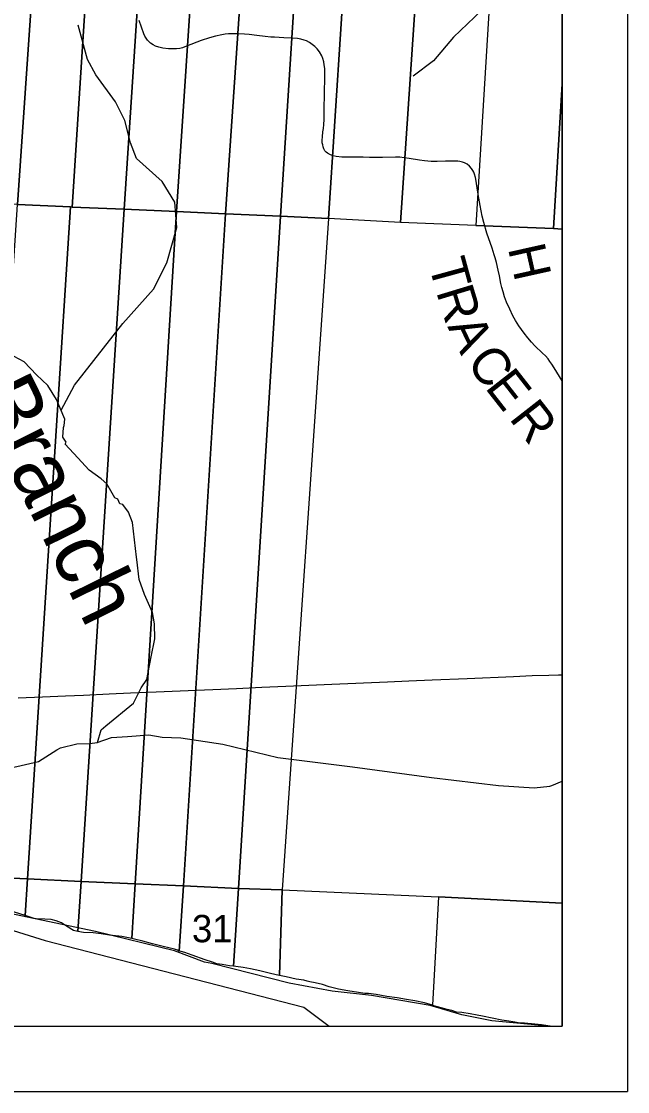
# Model space of a CAD drawing. Extents: x -2.1 to 31.9, y 6.3 to 28.3.
# Drawn here: x 6.006 to 6.934, y 20.344 to 21.982 of the extents above; entities that cross this region are included whole.
import ezdxf

# ---------------------------------------------------------------- set-up
doc = ezdxf.new("R2010")
doc.units = 0
for name, color, linetype in [('Default', 7, 'Continuous'), ('GM_X_County_Road', 7, 'Continuous'), ('GM_X_County_Road_Text', 7, 'Continuous'), ('GM_X_Major_River', 7, 'Continuous'), ('GM_X_Minor_River', 7, 'Continuous'), ('GM_X_Minor_River_Text', 7, 'Continuous'), ('GM_X_Section', 7, 'Continuous'), ('GM_X_Section_Text', 7, 'Continuous'), ('GM_X_State_Route', 7, 'Continuous'), ('SH_Cut_Line', 7, 'Continuous'), ('SH_Data', 7, 'Continuous')]:
    doc.layers.add(name, color=color, linetype=linetype)

msp = doc.modelspace()

# ---------------------------------------------------------------- linework, layer by layer
at = {"layer": 'Default'}
msp.add_lwpolyline([(5.1462, 20.8673), (5.351, 20.8306), (5.3336, 20.8064), (5.2334, 20.7804), (5.2354, 20.7659), (5.3321, 20.7189), (5.4454, 20.7228), (5.4488, 20.7357), (5.4242, 20.7435), (5.4528, 20.7586), (5.5937, 20.7278), (5.7973, 20.6518), (6.0426, 20.5752), (6.4385, 20.4731), (6.4775, 20.444), (6.8344, 20.444), (6.8344, 25.7721)], dxfattribs=at)
for points in [[(6.8344, 21.8866), (6.8344, 22.7109), (6.7658, 22.714), (6.7023, 21.67), (6.8212, 21.6651)], [(6.8344, 21.6645), (6.8344, 21.8866), (6.8212, 21.6651)], [(6.8344, 20.6325), (6.8344, 21.6645), (6.8212, 21.6651), (6.7023, 21.67), (6.5865, 21.6746), (6.4767, 21.6808), (6.4057, 20.6526), (6.645, 20.6422)], [(6.82, 20.444), (6.8344, 20.444), (6.8344, 20.6325), (6.645, 20.6422), (6.6359, 20.4764), (6.643, 20.4742), (6.654, 20.4712), (6.665, 20.4686), (6.6722, 20.4663), (6.6805, 20.4656), (6.6934, 20.4634), (6.7041, 20.4615), (6.7124, 20.4597), (6.7272, 20.4567), (6.742, 20.4537), (6.7526, 20.4522), (6.7617, 20.4507), (6.767, 20.4496), (6.7768, 20.4493), (6.7875, 20.4482), (6.8026, 20.4467), (6.8189, 20.4441)]]:
    msp.add_lwpolyline(points, close=True, dxfattribs=at)
at = {"layer": 'GM_X_County_Road'}
msp.add_lwpolyline([(6.8344, 21.4322), (6.8219, 21.4519), (6.8182, 21.4575), (6.8155, 21.4615), (6.8126, 21.4657), (6.8086, 21.4704), (6.8042, 21.4746), (6.7925, 21.4857), (6.7873, 21.4911), (6.7815, 21.4977), (6.7759, 21.5049), (6.768, 21.5163), (6.7627, 21.5246), (6.7589, 21.5315), (6.7539, 21.5418), (6.7492, 21.5525), (6.7461, 21.5606), (6.7437, 21.5684), (6.7419, 21.5748), (6.7406, 21.5809), (6.7382, 21.5927), (6.7363, 21.6016), (6.7338, 21.613), (6.7317, 21.6205), (6.7303, 21.6248), (6.7269, 21.6353), (6.7191, 21.6583), (6.7144, 21.6743), (6.7119, 21.6843), (6.7089, 21.7007), (6.7067, 21.7119), (6.7047, 21.7241), (6.7025, 21.738), (6.7015, 21.7433), (6.7001, 21.7483), (6.6989, 21.7514), (6.6977, 21.754), (6.6957, 21.7571), (6.6925, 21.7609), (6.6888, 21.7637), (6.6846, 21.7657), (6.6816, 21.7669), (6.6778, 21.7679), (6.6747, 21.7683), (6.6712, 21.7686), (6.6638, 21.7686), (6.6557, 21.7682), (6.6427, 21.7678), (6.6339, 21.768), (6.6237, 21.7687), (6.6156, 21.7697), (6.5999, 21.7727), (6.5924, 21.7736), (6.5857, 21.7743), (6.5789, 21.7745), (6.5591, 21.7742), (6.5394, 21.7742), (6.5297, 21.7744), (6.5092, 21.7744), (6.4967, 21.7747), (6.488, 21.7756), (6.4836, 21.7766), (6.4795, 21.778), (6.475, 21.7804), (6.473, 21.782), (6.471, 21.7844), (6.4694, 21.7874), (6.4683, 21.7903), (6.4676, 21.7934), (6.467, 21.7966), (6.467, 21.8006), (6.4674, 21.8054), (6.468, 21.8131), (6.4687, 21.8185), (6.4692, 21.8244), (6.4697, 21.8324), (6.4699, 21.8454), (6.4703, 21.8738), (6.471, 21.8954), (6.4709, 21.9046), (6.4707, 21.9101), (6.4701, 21.9158), (6.4692, 21.9206), (6.4679, 21.9254), (6.4663, 21.9295), (6.4626, 21.9358), (6.4592, 21.9402), (6.4555, 21.9441), (6.4515, 21.9471), (6.4474, 21.9498), (6.4426, 21.9524), (6.4392, 21.9538), (6.434, 21.9552), (6.4289, 21.956), (6.4203, 21.9569), (6.4079, 21.9574), (6.3936, 21.958), (6.3881, 21.9584), (6.3794, 21.9591), (6.3669, 21.9607), (6.3549, 21.9622), (6.3477, 21.9629), (6.3384, 21.9634), (6.33, 21.9635), (6.3234, 21.9631), (6.3184, 21.9626), (6.3132, 21.9617), (6.3036, 21.9596), (6.2942, 21.9571), (6.2817, 21.9529), (6.259, 21.9443), (6.2529, 21.9421), (6.2489, 21.9408), (6.2437, 21.9404), (6.2389, 21.9402), (6.2313, 21.9406), (6.223, 21.9415), (6.2167, 21.9428), (6.2115, 21.9446), (6.2082, 21.9463), (6.204, 21.9491), (6.1996, 21.9536), (6.1973, 21.9569), (6.1955, 21.9598), (6.194, 21.9631), (6.1903, 21.9734), (6.1868, 21.9839)], dxfattribs=at)
at = {"layer": 'GM_X_Major_River'}
msp.add_lwpolyline([(6.8077, 20.444), (6.7977, 20.4457), (6.7264, 20.4524), (6.6809, 20.4615), (6.6324, 20.4758), (6.5422, 20.4913), (6.4819, 20.4976), (6.4163, 20.5101), (6.298, 20.5403), (6.2866, 20.5421), (6.2408, 20.5595), (6.1198, 20.5893), (5.9765, 20.6191)], dxfattribs=at)
at = {"layer": 'GM_X_Minor_River'}
for points in [[(6.8344, 22.0788), (6.8176, 22.0793), (6.7959, 22.0736), (6.7763, 22.0632), (6.7589, 22.0493), (6.7396, 22.0359), (6.7109, 21.9992), (6.6681, 21.9584), (6.6371, 21.9222), (6.6061, 21.8985)], [(6.0672, 21.3872), (6.0875, 21.4257), (6.1618, 21.5201), (6.2084, 21.5726), (6.2289, 21.6125), (6.2442, 21.6667), (6.2412, 21.7055), (6.2221, 21.7373), (6.1827, 21.7727), (6.1732, 21.7962), (6.1648, 21.8306), (6.1506, 21.8592), (6.1205, 21.9004), (6.1076, 21.924), (6.0933, 21.9764)], [(5.9565, 20.8322), (6.0124, 20.8449), (6.0325, 20.8495), (6.0608, 20.8671), (6.0661, 20.8701), (6.0914, 20.8763), (6.1107, 20.8771), (6.1228, 20.8786), (6.1284, 20.898), (6.1356, 20.9037), (6.1779, 20.9384), (6.1896, 20.962), (6.1983, 20.9746), (6.2051, 21.0095), (6.2107, 21.0373), (6.2103, 21.0601), (6.2069, 21.0776), (6.1948, 21.1049), (6.1868, 21.1277), (6.183, 21.1588), (6.1826, 21.1623), (6.1765, 21.2154), (6.1701, 21.231), (6.1618, 21.2428), (6.1569, 21.2439), (6.1538, 21.2507), (6.1493, 21.253), (6.1372, 21.2746), (6.1285, 21.2818), (6.1103, 21.2955), (6.0925, 21.3144), (6.0736, 21.3349), (6.0747, 21.3384), (6.0698, 21.3459), (6.0706, 21.3604), (6.0717, 21.3638), (6.0728, 21.3733), (6.0603, 21.4037), (6.0467, 21.4249), (6.0297, 21.4412), (6.0104, 21.461), (5.9952, 21.4693)], [(6.1225, 20.8786), (6.1443, 20.8859), (6.1689, 20.8875), (6.2014, 20.8902), (6.2218, 20.8864), (6.2505, 20.8854), (6.3148, 20.8756), (6.3991, 20.8553), (6.5133, 20.8411), (6.6343, 20.8247), (6.7368, 20.8124), (6.7916, 20.8091), (6.8154, 20.8118), (6.8184, 20.8125), (6.8344, 20.8191)]]:
    msp.add_lwpolyline(points, dxfattribs=at)
at = {"layer": 'GM_X_Section'}
for points in [[(6.0723, 22.7483), (6.0006, 21.7019), (5.9213, 21.7055), (5.9912, 22.7527)], [(6.1513, 22.7445), (6.0839, 21.6982), (6.0813, 21.6984), (6.0006, 21.7019), (6.0723, 22.7483)], [(6.2319, 22.7402), (6.1637, 21.6947), (6.0839, 21.6982), (6.1513, 22.7445)], [(6.313, 22.7362), (6.2438, 21.6911), (6.1637, 21.6947), (6.2319, 22.7402)], [(6.3902, 22.7322), (6.3189, 21.6878), (6.2438, 21.6911), (6.313, 22.7362)], [(6.4695, 22.728), (6.4029, 21.6841), (6.3189, 21.6878), (6.3902, 22.7322)], [(6.5442, 22.7242), (6.4767, 21.6808), (6.4029, 21.6841), (6.4695, 22.728)], [(6.6574, 22.719), (6.5865, 21.6746), (6.4767, 21.6808), (6.5442, 22.7242)], [(6.7658, 22.714), (6.7023, 21.67), (6.5865, 21.6746), (6.6574, 22.719)], [(6.0813, 21.6984), (6.0156, 20.6695), (5.933, 20.6732), (6.0006, 21.7019)], [(6.0839, 21.6982), (6.1637, 21.6947), (6.0979, 20.6658), (6.0156, 20.6695), (6.0813, 21.6984)], [(6.2438, 21.6911), (6.1805, 20.6622), (6.0979, 20.6658), (6.1637, 21.6947)], [(6.3189, 21.6878), (6.2543, 20.6589), (6.1805, 20.6622), (6.2438, 21.6911)], [(6.4029, 21.6841), (6.3388, 20.6551), (6.2543, 20.6589), (6.3189, 21.6878)], [(6.4767, 21.6808), (6.4057, 20.6526), (6.3388, 20.6551), (6.4029, 21.6841)], [(6.0156, 20.6695), (6.012, 20.6134), (5.9957, 20.6186), (5.9862, 20.6204), (5.979, 20.6215), (5.973, 20.623), (5.9616, 20.626), (5.954, 20.6283), (5.9438, 20.6324), (5.9347, 20.6354), (5.9306, 20.6368), (5.933, 20.6732)], [(6.0979, 20.6658), (6.0929, 20.589), (6.086, 20.5908), (6.0837, 20.5923), (6.0723, 20.5995), (6.0678, 20.6021), (6.0594, 20.6055), (6.0518, 20.6074), (6.0423, 20.6081), (6.0287, 20.6084), (6.0257, 20.6092), (6.0211, 20.6107), (6.012, 20.6134), (6.0156, 20.6695)], [(6.1805, 20.6622), (6.1754, 20.5785), (6.1679, 20.5801), (6.1603, 20.5812), (6.1459, 20.5827), (6.141, 20.5835), (6.1284, 20.5853), (6.1163, 20.5868), (6.1012, 20.5875), (6.0929, 20.589), (6.0979, 20.6658)], [(6.2543, 20.6589), (6.248, 20.5588), (6.2452, 20.5603), (6.2407, 20.5618), (6.2236, 20.5663), (6.2073, 20.5704), (6.1921, 20.5742), (6.1796, 20.5775), (6.1754, 20.5785), (6.1805, 20.6622)], [(6.3388, 20.6551), (6.3313, 20.5359), (6.3249, 20.5364), (6.3135, 20.5386), (6.3055, 20.5397), (6.2987, 20.5419), (6.2877, 20.5457), (6.268, 20.5528), (6.2566, 20.557), (6.2509, 20.5585), (6.248, 20.5588), (6.2543, 20.6589)], [(6.4057, 20.6526), (6.4017, 20.5217), (6.3966, 20.5228), (6.3855, 20.5252), (6.3715, 20.5289), (6.3571, 20.5319), (6.3457, 20.5338), (6.3344, 20.5356), (6.3313, 20.5359), (6.3388, 20.6551)], [(6.4057, 20.6526), (6.645, 20.6422), (6.6359, 20.4764), (6.6233, 20.4798), (6.6085, 20.4828), (6.596, 20.485), (6.5816, 20.4876), (6.566, 20.4898), (6.5494, 20.4924), (6.5376, 20.4939), (6.5323, 20.4939), (6.5224, 20.4957), (6.5061, 20.4983), (6.4917, 20.5009), (6.4773, 20.5043), (6.4671, 20.5077), (6.4561, 20.5107), (6.4481, 20.5122), (6.4436, 20.5129), (6.439, 20.5144), (6.4269, 20.5163), (6.4117, 20.5196), (6.4017, 20.5217)]]:
    msp.add_lwpolyline(points, close=True, dxfattribs=at)
at = {"layer": 'GM_X_State_Route'}
msp.add_lwpolyline([(6.0012, 20.9468), (6.0385, 20.9484), (6.0739, 20.95), (6.1016, 20.9511), (6.1409, 20.9528), (6.1732, 20.9542), (6.2126, 20.956), (6.2618, 20.958), (6.2995, 20.9597), (6.3356, 20.9613), (6.3747, 20.9629), (6.4113, 20.9645), (6.4814, 20.9677), (6.5671, 20.9713), (6.5997, 20.9727), (6.6354, 20.9741), (6.6888, 20.9765), (6.7595, 20.9795), (6.7881, 20.9808), (6.8137, 20.9816), (6.8285, 20.9819), (6.8344, 20.9819)], dxfattribs=at)
at = {"layer": 'SH_Cut_Line'}
msp.add_lwpolyline([(5.1462, 20.8673), (5.351, 20.8306), (5.3336, 20.8064), (5.2334, 20.7804), (5.2354, 20.7659), (5.3321, 20.7189), (5.4454, 20.7228), (5.4488, 20.7357), (5.4242, 20.7435), (5.4528, 20.7586), (5.5937, 20.7278), (5.7973, 20.6518), (6.0426, 20.5752), (6.4385, 20.4731), (6.4775, 20.444), (6.8344, 20.444), (6.8344, 27.244)], dxfattribs=at)
at = {"layer": 'SH_Data'}
for p, q in [((6.9344, 27.344), (6.9344, 20.344)), ((6.8344, 27.244), (6.8344, 20.444)), ((0.0344, 20.444), (6.8344, 20.444)), ((-0.0656, 20.344), (6.9344, 20.344))]:
    msp.add_line(p, q, dxfattribs=at)

# ---------------------------------------------------------------- texts
at = {"layer": 'GM_X_County_Road_Text'}
for s, rotation, p in [('H', 282.5735, (6.751, 21.6353)), ('T', 285.3497, (6.6293, 21.6115)), ('R', 286.9005, (6.641, 21.5689)), ('A', 295.826, (6.6581, 21.5152)), ('C', 306.8329, (6.6861, 21.4601)), ('E', 308.0682, (6.7149, 21.4217)), ('R', 307.9948, (6.7519, 21.3744))]:
    msp.add_text(s, height=0.0568, rotation=rotation, dxfattribs=at).set_placement(p)
at = {"layer": 'GM_X_Minor_River_Text'}
msp.add_text('Branch', height=0.09469, rotation=296.1346, dxfattribs=at).set_placement((5.9307, 21.4114))
at = {"layer": 'GM_X_Section_Text'}
msp.add_text('31', height=0.04186, rotation=0, dxfattribs=at).set_placement((6.2674, 20.5726))

doc.saveas('drawing.dxf')
